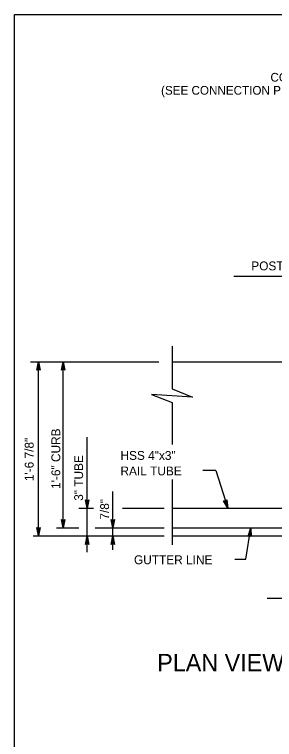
# Model space of a CAD drawing. Extents: x 632007860 to 635435983, y 295418622 to 297794622.
# Drawn here: x 634570860 to 634661713, y 296931985 to 297185622 of the extents above; entities that cross this region are included whole.
import ezdxf

# ---------------------------------------------------------------- set-up
doc = ezdxf.new("R2010")
doc.units = 0
for name, color, linetype in [('1', 7, 'Continuous'), ('S-DETL-DIMS', 7, 'Continuous'), ('S-DETL-T120', 7, 'Continuous'), ('S-DETL-T240', 7, 'Continuous'), ('S-STEL', 7, 'Continuous')]:
    doc.layers.add(name, color=color, linetype=linetype)

msp = doc.modelspace()

# ---------------------------------------------------------------- linework, layer by layer
at = {"layer": '1'}
for p, q in [((634570860, 297185622), (635356860, 297185622)), ((634570860, 296621622), (634570860, 297185622))]:
    msp.add_line(p, q, dxfattribs=at)
at = {"layer": 'S-DETL-DIMS'}
for p, q in [((634647552, 297094126), (634792897, 297094126)), ((634625904, 297069551), (634625904, 297054686)), ((634576447, 297064108), (634621266, 297064108)), ((634579264, 297003183), (634579264, 297064108)), ((634587881, 297006007), (634587881, 297064108)), ((634625904, 297049924), (634625904, 297035191)), ((634596243, 296997565), (634596243, 297037724)), ((634641220, 297026048), (634636683, 297026048)), ((634641220, 297026048), (634645365, 297012866)), ((634625904, 297022960), (634625904, 297000120)), ((634605220, 296998313), (634605220, 297018715)), ((634593332, 297012866), (634598453, 297012866)), ((634608643, 297012866), (634623211, 297012866)), ((634585543, 297006007), (634593380, 297006007)), ((634599018, 297006007), (634623211, 297006007)), ((634614892, 297006007), (634623211, 297006007)), ((634651710, 296995102), (634653483, 297006007)), ((634577413, 297003183), (634623211, 297003183)), ((634647813, 296995102), (634651710, 296995102)), ((634659121, 296981393), (634720312, 296981393))]:
    msp.add_line(p, q, dxfattribs=at)
for points in [[(634579264, 297064108), (634579818, 297061148), (634579739, 297061262), (634579660, 297061376), (634579561, 297061435), (634579462, 297061494), (634579363, 297061511), (634579264, 297061528), (634579164, 297061511), (634579065, 297061494), (634578966, 297061435), (634578867, 297061376), (634578788, 297061262), (634578709, 297061148), (634579264, 297064108), (634578788, 297061262), (634578867, 297061376), (634579264, 297064108), (634578966, 297061435), (634579065, 297061494), (634579264, 297064108), (634579164, 297061511), (634579264, 297061528), (634579264, 297064108), (634579363, 297061511), (634579462, 297061494), (634579264, 297064108), (634579561, 297061435), (634579660, 297061376), (634579264, 297064108), (634579739, 297061262)], [(634587881, 297064108), (634588436, 297061148), (634588357, 297061262), (634588278, 297061376), (634588179, 297061435), (634588080, 297061494), (634587980, 297061511), (634587881, 297061528), (634587782, 297061511), (634587683, 297061494), (634587583, 297061435), (634587484, 297061376), (634587405, 297061262), (634587326, 297061148), (634587881, 297064108), (634587405, 297061262), (634587484, 297061376), (634587881, 297064108), (634587583, 297061435), (634587683, 297061494), (634587881, 297064108), (634587782, 297061511), (634587881, 297061528), (634587881, 297064108), (634587980, 297061511), (634588080, 297061494), (634587881, 297064108), (634588179, 297061435), (634588278, 297061376), (634587881, 297064108), (634588357, 297061262)], [(634625904, 297054686), (634633047, 297051786), (634618760, 297052651), (634625904, 297049924)], [(634596243, 297012866), (634595688, 297015826), (634595767, 297015712), (634595846, 297015598), (634595946, 297015539), (634596045, 297015480), (634596144, 297015463), (634596243, 297015446), (634596343, 297015463), (634596442, 297015480), (634596541, 297015539), (634596640, 297015598), (634596719, 297015712), (634596798, 297015826), (634596243, 297012866), (634596719, 297015712), (634596640, 297015598), (634596243, 297012866), (634596541, 297015539), (634596442, 297015480), (634596243, 297012866), (634596343, 297015463), (634596243, 297015446), (634596243, 297012866), (634596144, 297015463), (634596045, 297015480), (634596243, 297012866), (634595946, 297015539), (634595846, 297015598), (634596243, 297012866), (634595767, 297015712)], [(634645365, 297012866), (634643948, 297015523), (634644058, 297015438), (634644167, 297015353), (634644280, 297015326), (634644392, 297015300), (634644492, 297015314), (634644592, 297015327), (634644681, 297015373), (634644771, 297015419), (634644848, 297015505), (634644925, 297015591), (634644966, 297015723), (634645007, 297015856), (634645365, 297012866), (634644966, 297015723), (634644925, 297015591), (634645365, 297012866), (634644848, 297015505), (634644771, 297015419), (634645365, 297012866), (634644681, 297015373), (634644592, 297015327), (634645365, 297012866), (634644492, 297015314), (634644392, 297015300), (634645365, 297012866), (634644280, 297015326), (634644167, 297015353), (634645365, 297012866), (634644058, 297015438)], [(634587881, 297006007), (634587326, 297008966), (634587405, 297008852), (634587484, 297008738), (634587583, 297008679), (634587683, 297008620), (634587782, 297008603), (634587881, 297008586), (634587980, 297008603), (634588080, 297008620), (634588179, 297008679), (634588278, 297008738), (634588357, 297008852), (634588436, 297008966), (634587881, 297006007), (634588357, 297008852), (634588278, 297008738), (634587881, 297006007), (634588179, 297008679), (634588080, 297008620), (634587881, 297006007), (634587980, 297008603), (634587881, 297008586), (634587881, 297006007), (634587782, 297008603), (634587683, 297008620), (634587881, 297006007), (634587583, 297008679), (634587484, 297008738), (634587881, 297006007), (634587405, 297008852)], [(634605220, 297006007), (634604665, 297008966), (634604744, 297008852), (634604823, 297008738), (634604923, 297008679), (634605022, 297008620), (634605121, 297008603), (634605220, 297008586), (634605319, 297008603), (634605419, 297008620), (634605518, 297008679), (634605617, 297008738), (634605696, 297008852), (634605775, 297008966), (634605220, 297006007), (634605696, 297008852), (634605617, 297008738), (634605220, 297006007), (634605518, 297008679), (634605419, 297008620), (634605220, 297006007), (634605319, 297008603), (634605220, 297008586), (634605220, 297006007), (634605121, 297008603), (634605022, 297008620), (634605220, 297006007), (634604923, 297008679), (634604823, 297008738), (634605220, 297006007), (634604744, 297008852)], [(634579264, 297003183), (634578709, 297006142), (634578788, 297006028), (634578867, 297005914), (634578966, 297005855), (634579065, 297005797), (634579164, 297005780), (634579264, 297005762), (634579363, 297005780), (634579462, 297005797), (634579561, 297005855), (634579660, 297005914), (634579739, 297006028), (634579818, 297006142), (634579264, 297003183), (634579739, 297006028), (634579660, 297005914), (634579264, 297003183), (634579561, 297005855), (634579462, 297005797), (634579264, 297003183), (634579363, 297005780), (634579264, 297005762), (634579264, 297003183), (634579164, 297005780), (634579065, 297005797), (634579264, 297003183), (634578966, 297005855), (634578867, 297005914), (634579264, 297003183), (634578788, 297006028)], [(634653483, 297006007), (634653556, 297002997), (634653496, 297003122), (634653437, 297003247), (634653348, 297003321), (634653260, 297003395), (634653164, 297003428), (634653069, 297003460), (634652969, 297003459), (634652868, 297003459), (634652760, 297003416), (634652653, 297003374), (634652557, 297003274), (634652461, 297003175), (634653483, 297006007), (634652557, 297003274), (634652653, 297003374), (634653483, 297006007), (634652760, 297003416), (634652868, 297003459), (634653483, 297006007), (634652969, 297003459), (634653069, 297003460), (634653483, 297006007), (634653164, 297003428), (634653260, 297003395), (634653483, 297006007), (634653348, 297003321), (634653437, 297003247), (634653483, 297006007), (634653496, 297003122)], [(634596243, 297003183), (634596798, 297000223), (634596719, 297000337), (634596640, 297000452), (634596541, 297000510), (634596442, 297000569), (634596343, 297000586), (634596243, 297000603), (634596144, 297000586), (634596045, 297000569), (634595946, 297000510), (634595846, 297000452), (634595767, 297000337), (634595688, 297000223), (634596243, 297003183), (634595767, 297000337), (634595846, 297000452), (634596243, 297003183), (634595946, 297000510), (634596045, 297000569), (634596243, 297003183), (634596144, 297000586), (634596243, 297000603), (634596243, 297003183), (634596343, 297000586), (634596442, 297000569), (634596243, 297003183), (634596541, 297000510), (634596640, 297000452), (634596243, 297003183), (634596719, 297000337)], [(634605220, 297003183), (634605775, 297000223), (634605696, 297000337), (634605617, 297000452), (634605518, 297000510), (634605419, 297000569), (634605319, 297000586), (634605220, 297000603), (634605121, 297000586), (634605022, 297000569), (634604923, 297000510), (634604823, 297000452), (634604744, 297000337), (634604665, 297000223), (634605220, 297003183), (634604744, 297000337), (634604823, 297000452), (634605220, 297003183), (634604923, 297000510), (634605022, 297000569), (634605220, 297003183), (634605121, 297000586), (634605220, 297000603), (634605220, 297003183), (634605319, 297000586), (634605419, 297000569), (634605220, 297003183), (634605518, 297000510), (634605617, 297000452), (634605220, 297003183), (634605696, 297000337)]]:
    msp.add_lwpolyline(points, dxfattribs=at)
at = {"layer": 'S-STEL'}
for p, q in [((634625904, 297064108), (634792895, 297064108)), ((634625904, 297012866), (634755682, 297012866)), ((634625904, 297006007), (634792895, 297006007)), ((634625904, 297003183), (634757389, 297003183))]:
    msp.add_line(p, q, dxfattribs=at)

# ---------------------------------------------------------------- texts
at = {"layer": 'S-DETL-T120'}
for s, height, p in [('CONNECTION PLATE', 3048.01, (634660304, 297162139)), ('(SEE CONNECTION PLATE DETAIL)', 3048.01, (634622072, 297157567)), ('  POST W6x20', 3098.73, (634651313, 297096113)), ('HSS 4"x3"', 3098.7, (634607889, 297029810)), ('RAIL TUBE', 3098.7, (634607889, 297024387)), ('GUTTER LINE', 3098.73, (634612610, 296993317))]:
    msp.add_text(s, height=height, dxfattribs=at).set_placement(p)
for s, p in [('1\'-6" CURB', (634586852, 297019658)), ('1\'-6 7/8"', (634577545, 297022380)), ('3" TUBE', (634594821, 297015498)), ('7/8"', (634603892, 297008897))]:
    msp.add_text(s, height=3098.7, rotation=90, dxfattribs=at).set_placement(p)
at = {"layer": 'S-DETL-T240'}
msp.add_text('PLAN VIEW FOR THRIE-BEAM TO PA 3-RAIL BRIDGE BARRIER', height=6096, dxfattribs=at).set_placement((634620735, 296955834))

doc.saveas('drawing.dxf')
